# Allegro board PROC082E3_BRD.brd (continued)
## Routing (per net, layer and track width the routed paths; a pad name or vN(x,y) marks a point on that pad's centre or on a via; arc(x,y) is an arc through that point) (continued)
CSI0_D2_P: length 125.7
  TOP w0.102: J2.17 48.09,31.28 arc(48.06,31.42) 47.98,31.54 47.97,31.55 arc(47.89,31.68) 47.86,31.82 47.86,32.73 arc(47.9,32.84) 48.01,32.89 48.06,32.89 arc(48.14,32.87) 48.22,32.82 48.3,32.74 v1(48.3,32.69)
  L03_SIG1 w0.089: v1(50.95,94.7) arc(50.87,94.9) 50.66,94.98 50.04,94.98 arc(49.8,94.93) 49.59,94.8 49.35,94.55 arc(49.06,94.12) 48.95,93.6 48.95,91.41 arc(48.84,90.86) 48.53,90.38 46.65,88.5 arc(46.06,87.62) 45.85,86.58 45.85,79.54 arc(46.05,78.55) 46.61,77.71 51.4,72.92 arc(52.07,71.91) 52.3,70.72 52.3,56.23 arc(52.17,55.57) 51.8,55.01 arc(51.64,54.78) 51.59,54.51 51.59,51.96 arc(51.37,51.43) 50.85,51.21 49.62,51.21 arc(49.22,50.81) 49.62,50.41 51.51,50.41 arc(52.25,49.67) 51.51,48.93 49.62,48.93 arc(49.22,48.53) 49.62,48.13 50.85,48.13 arc(51.59,47.38) 50.85,46.64 49.62,46.64 arc(49.22,46.24) 49.62,45.84 50.85,45.84 arc(51.59,45.1) 50.85,44.35 49.62,44.35 arc(49.22,43.95) 49.62,43.55 50.85,43.55 arc(51.37,43.34) 51.59,42.81 51.59,41.84 arc(51.23,40.04) 50.21,38.51 arc(50.05,38.28) 50,38.01 50,37.68 arc(50.16,37.28) 50.56,37.12 51.67,37.12 arc(52.2,36.9) 52.42,36.37 52.42,35.16 arc(52.2,34.63) 51.67,34.41 49.36,34.41 arc(49.28,34.39) 49.22,34.35 48.13,33.26 arc(48.04,33.13) 48.01,32.98 arc(48.1,32.78) v1(48.3,32.69)
  BOTTOM w0.102: v1(50.95,94.7) 50.95,94.74 arc(50.87,94.93) 50.67,95.01 arc(50.36,95.08) 50.09,95.26 49.34,96.01 arc(49.15,96.3) 49.08,96.64 49.08,96.75 arc(48.98,97.26) 48.69,97.69 47.62,98.77 arc(46.93,99.23) 46.12,99.39 43.05,99.39 arc(42.28,99.54) 41.63,99.98 41.04,100.56 arc(40.48,100.94) 39.81,101.07 37.83,101.07 arc(37.39,101.16) 37.02,101.41 arc(36.12,102.01) 35.06,102.22 33.31,102.22 arc(31.43,102.6) 29.84,103.66 29.08,104.42 arc(28.76,104.9) 28.64,105.47 28.64,106.17 arc(28.55,106.65) 28.28,107.06 28.18,107.15 arc(28,107.42) 27.94,107.73 27.94,110.63 arc(27.93,110.67) 27.91,110.7 27.85,110.76 arc(27.83,110.79) 27.82,110.83 U9.40
CSI0_D3_N: length 125.7
  TOP w0.102: J2.23 46.09,31.13 arc(46.1,31.2) 46.14,31.26 46.16,31.27 arc(46.19,31.33) 46.21,31.4 46.21,32 arc(46.15,32.14) 46.01,32.2 45.52,32.2 arc(45.33,32.17) 45.16,32.06 v1(44.99,31.88)
  L03_SIG1 w0.089: v1(44.99,31.88) 45.14,32.04 arc(45.29,32.13) 45.46,32.17 45.63,32.17 arc(45.91,32.22) 46.15,32.38 46.31,32.54 arc(46.48,32.8) 46.54,33.11 46.54,36.41 arc(46.73,37.37) 47.28,38.18 arc(47.66,38.75) 47.8,39.43 47.8,40.23 arc(47.91,40.51) 48.2,40.63 49.15,40.63 arc(49.89,41.37) 49.15,42.12 48.2,42.12 arc(47.91,42.23) 47.8,42.52 47.8,43.33 arc(47.58,43.86) 47.05,44.08 45.87,44.08 arc(45.62,44.18) 45.51,44.44 45.51,44.54 arc(45.61,44.78) 45.85,44.88 47.05,44.88 arc(47.58,45.1) 47.8,45.62 47.8,46.47 arc(47.53,47.1) 46.9,47.37 45.46,47.37 arc(44.9,47.92) 45.46,48.47 46.9,48.47 arc(47.8,49.37) 46.9,50.26 45.46,50.26 arc(44.9,50.81) 45.46,51.37 46.9,51.37 arc(47.53,51.63) 47.8,52.26 47.8,52.86 arc(48.22,55.01) 49.44,56.84 49.98,57.37 arc(50.48,58.12) 50.65,59 50.65,61.78 arc(50.55,62.31) 50.25,62.76 50.17,62.84 arc(50.03,63.04) 49.99,63.27 49.99,64.81 arc(50.07,65.23) 50.31,65.59 50.68,65.96 arc(50.96,66.37) 51.05,66.86 51.05,69.85 arc(50.96,70.34) 50.68,70.76 50.38,71.05 arc(50.18,71.18) 49.95,71.23 48.98,71.23 arc(48.66,71.29) 48.39,71.48 48.26,71.6 arc(48.11,71.82) 48.06,72.07 48.06,72.38 arc(48.01,72.63) 47.87,72.85 44.59,76.13 arc(44.19,76.72) 44.05,77.43 44.05,78.37 arc(43.71,79.18) 42.9,79.52 41.72,79.52 arc(40.91,80.33) 41.72,81.13 42.9,81.13 arc(43.71,81.47) 44.05,82.28 44.05,87.18 arc(44.15,87.69) 44.44,88.12 46.5,90.18 arc(46.89,90.77) 47.03,91.47 47.03,96.83 arc(47.12,97.03) v1(47.32,97.12)
  BOTTOM w0.102: v1(47.32,97.12) 47.26,97.12 arc(47.07,97.19) 46.99,97.38 46.99,97.61 arc(46.95,97.8) 46.84,97.97 46.74,98.07 arc(46.52,98.22) 46.25,98.28 38.94,98.28 arc(38,98.46) 37.21,98.99 36.46,99.75 arc(35.1,100.65) 33.49,100.97 33.06,100.97 arc(30.93,101.4) 29.13,102.6 arc(27.71,104.73) 27.21,107.24 27.21,110.63 arc(27.22,110.67) 27.24,110.7 27.29,110.76 arc(27.32,110.79) 27.32,110.83 U9.41
CSI0_D3_P: length 125.7
  TOP w0.102: v1(44.99,32.79) 44.99,32.57 arc(45.02,32.5) 45.09,32.47 46.01,32.47 arc(46.34,32.33) 46.47,32 46.47,31.37 arc(46.49,31.3) 46.53,31.24 46.54,31.23 arc(46.58,31.17) 46.59,31.11 J2.21
  L03_SIG1 w0.089: v1(44.99,32.79) 45.14,32.64 arc(45.29,32.54) 45.46,32.51 45.63,32.51 arc(45.78,32.54) 45.91,32.63 46.06,32.78 arc(46.16,32.93) 46.2,33.11 46.2,36.41 arc(46.42,37.5) 47.04,38.42 arc(47.34,38.88) 47.45,39.43 47.45,40.23 arc(47.67,40.76) 48.2,40.97 49.15,40.97 arc(49.55,41.37) 49.15,41.77 48.2,41.77 arc(47.67,41.99) 47.45,42.52 47.45,43.33 arc(47.34,43.62) 47.05,43.73 45.87,43.73 arc(45.38,43.94) 45.17,44.44 45.17,44.54 arc(45.37,45.02) 45.85,45.22 47.05,45.22 arc(47.34,45.34) 47.45,45.62 47.45,46.47 arc(47.29,46.86) 46.9,47.02 45.46,47.02 arc(44.56,47.92) 45.46,48.81 46.9,48.81 arc(47.45,49.37) 46.9,49.92 45.46,49.92 arc(44.56,50.81) 45.46,51.71 46.9,51.71 arc(47.29,51.87) 47.45,52.26 47.45,52.86 arc(47.91,55.14) 49.2,57.08 49.74,57.62 arc(50.16,58.25) 50.31,59 50.31,61.78 arc(50.23,62.18) 50.01,62.51 49.92,62.59 arc(49.72,62.9) 49.65,63.27 49.65,64.81 arc(49.76,65.36) 50.07,65.83 50.43,66.2 arc(50.64,66.5) 50.71,66.86 50.71,69.85 arc(50.64,70.21) 50.43,70.52 50.14,70.81 arc(50.05,70.87) 49.95,70.89 48.98,70.89 arc(48.53,70.98) 48.15,71.23 48.02,71.36 arc(47.8,71.69) 47.72,72.07 47.72,72.38 arc(47.7,72.5) 47.63,72.6 47.43,72.8 44.35,75.88 arc(43.87,76.59) 43.71,77.43 43.71,78.37 arc(43.47,78.94) 42.9,79.18 41.72,79.18 arc(40.57,80.33) 41.72,81.47 42.9,81.47 arc(43.47,81.71) 43.71,82.28 43.71,87.18 arc(43.83,87.82) 44.2,88.36 46.25,90.42 arc(46.58,90.9) 46.69,91.47 46.69,96.83 arc(46.6,97.03) v1(46.4,97.12)
  BOTTOM w0.102: U9.42 26.82,110.83 arc(26.83,110.79) 26.85,110.76 26.91,110.7 arc(26.93,110.67) 26.94,110.63 26.94,107.24 arc(27.46,104.63) 28.94,102.41 arc(30.83,101.15) 33.06,100.71 33.49,100.71 arc(34.99,100.41) 36.27,99.56 37.02,98.8 arc(37.9,98.21) 38.94,98.01 46.25,98.01 arc(46.41,97.98) 46.55,97.88 46.66,97.78 arc(46.71,97.7) 46.73,97.61 46.73,97.38 arc(46.65,97.19) 46.46,97.12 v1(46.4,97.12)
CSI1_CLK_N: length 55.7
  TOP w0.102: J2.27 44.59,29.7 arc(44.6,29.63) 44.64,29.58 44.66,29.56 arc(44.69,29.51) 44.71,29.44 44.71,28.46 arc(44.67,28.26) 44.56,28.1 v1(44.38,27.92)
  L6_SIG2 w0.089: v1(30.82,63.21) 30.98,63.21 arc(31.11,63.27) 31.17,63.4 31.17,63.49 arc(31.11,63.62) 30.99,63.67 30.51,63.67 arc(30.37,63.65) 30.24,63.56 30.16,63.49 arc(30.02,63.27) 29.97,63.02 29.97,58.98 arc(30.02,58.75) 30.15,58.55 32.03,56.67 arc(32.48,55.99) 32.64,55.2 32.64,40.38 arc(32.75,39.82) 33.07,39.34 33.26,39.15 38.41,34 arc(38.9,33.26) 39.08,32.4 39.08,30.76 arc(39.21,30.43) 39.53,30.3 41.38,30.3 arc(41.99,30.04) 42.25,29.43 42.25,27.61 arc(42.44,27.15) 42.9,26.96 44.72,26.96 arc(44.88,27.02) 44.94,27.18 44.94,27.29 arc(44.9,27.39) 44.8,27.43 44.36,27.43 arc(44.26,27.47) 44.22,27.57 44.22,27.78 arc(44.26,27.88) 44.36,27.92 v1(44.38,27.92)
  BOTTOM w0.102: U24.31 34.5,63.07 arc(34.46,63.08) 34.43,63.1 34.37,63.16 arc(34.34,63.18) 34.3,63.19 32.52,63.19 arc(32.12,63.27) 31.79,63.49 arc(31.74,63.52) 31.68,63.54 31.19,63.54 arc(31.15,63.53) 31.12,63.51 v1(30.82,63.21)
CSI1_CLK_P: length 55.7
  TOP w0.102: J2.25 45.09,29.7 arc(45.08,29.63) 45.04,29.58 45.03,29.56 arc(44.99,29.51) 44.97,29.44 44.97,28.46 arc(45.01,28.26) 45.12,28.1 v1(45.3,27.92)
  L6_SIG2 w0.089: v1(45.3,27.92) 45.2,27.83 arc(45.15,27.7) 45.2,27.58 arc(45.26,27.49) 45.29,27.38 45.29,27.18 arc(45.12,26.78) 44.72,26.62 42.9,26.62 arc(42.2,26.91) 41.91,27.61 41.91,29.43 arc(41.75,29.8) 41.38,29.96 39.53,29.96 arc(38.97,30.19) 38.73,30.76 38.73,32.4 arc(38.59,33.13) 38.17,33.75 33.02,38.91 32.83,39.1 arc(32.43,39.69) 32.29,40.38 32.29,55.2 arc(32.16,55.86) 31.79,56.42 29.91,58.31 arc(29.7,58.61) 29.63,58.98 29.63,63.02 arc(29.7,63.4) 29.92,63.73 30,63.8 arc(30.23,63.96) 30.51,64.02 30.56,64.02 arc(30.7,64.05) v1(30.82,64.13)
  BOTTOM w0.102: U24.32 34.5,63.57 arc(34.46,63.56) 34.43,63.54 34.37,63.48 arc(34.34,63.46) 34.3,63.46 32.52,63.46 arc(32.23,63.51) 31.98,63.68 arc(31.84,63.77) 31.68,63.8 31.19,63.8 arc(31.15,63.81) 31.12,63.83 v1(30.82,64.13)
CSI1_D0_N: length 55.8
  TOP w0.102: v1(42.88,29.13) 43.08,29.13 arc(43.17,29.17) 43.21,29.26 43.21,29.47 arc(43.2,29.51) 43.18,29.54 43.12,29.6 arc(43.1,29.63) 43.09,29.67 J2.31
  L6_SIG2 w0.089: v1(42.88,29.13) 42.88,29.1 arc(42.93,28.98) 43.05,28.93 43.15,28.93 arc(43.27,28.98) 43.32,29.1 43.32,30.84 arc(43.21,31.09) 42.96,31.2 40.81,31.2 arc(40.2,31.45) 39.95,32.06 39.95,33.46 arc(39.88,33.82) 39.67,34.14 34.48,39.33 arc(34.25,39.67) 34.17,40.07 34.17,57.65 arc(34.08,57.87) 33.86,57.96 32.66,57.96 arc(32,58.61) 32.66,59.27 33.86,59.27 arc(34.08,59.36) 34.17,59.58 34.17,60.25 arc(34.03,60.6) 33.68,60.74 31.52,60.74 arc(31.07,60.93) 30.88,61.38 30.88,61.52 arc(31.08,61.99) 31.55,62.18 33.61,62.18 arc(33.79,62.26) 33.87,62.44 33.87,64.26 arc(33.8,64.43) 33.62,64.5 33.08,64.5 arc(32.94,64.47) 32.81,64.39 v1(32.63,64.21)
  BOTTOM w0.102: v1(32.63,64.21) 32.92,64.5 arc(32.96,64.52) 33,64.53 33.11,64.53 arc(33.27,64.5) 33.42,64.4 arc(33.65,64.24) 33.93,64.19 34.3,64.19 arc(34.34,64.18) 34.37,64.16 34.43,64.1 arc(34.46,64.08) 34.5,64.07 U24.33
CSI1_D0_P: length 55.7
  TOP w0.102: J2.29 43.59,29.67 arc(43.58,29.63) 43.56,29.6 43.5,29.54 arc(43.48,29.51) 43.47,29.47 43.47,29.26 arc(43.51,29.17) 43.61,29.13 v1(43.8,29.13)
  L6_SIG2 w0.089: v1(43.8,29.13) 43.76,29.17 arc(43.69,29.28) 43.66,29.4 43.66,30.84 arc(43.45,31.34) 42.96,31.54 40.81,31.54 arc(40.45,31.69) 40.29,32.06 40.29,33.46 arc(40.2,33.96) 39.91,34.38 34.72,39.57 arc(34.57,39.8) 34.52,40.07 34.52,57.65 arc(34.32,58.11) 33.86,58.3 32.66,58.3 arc(32.35,58.61) 32.66,58.92 33.86,58.92 arc(34.32,59.11) 34.52,59.58 34.52,60.25 arc(34.27,60.84) 33.68,61.08 31.52,61.08 arc(31.31,61.17) 31.23,61.38 31.23,61.52 arc(31.32,61.75) 31.55,61.84 33.61,61.84 arc(34.03,62.02) 34.21,62.44 34.21,64.26 arc(34.04,64.67) 33.62,64.84 33.08,64.84 arc(32.92,64.88) 32.79,64.97 v1(32.63,65.12)
  BOTTOM w0.102: U24.34 34.5,64.57 arc(34.46,64.56) 34.43,64.54 34.37,64.48 arc(34.34,64.46) 34.3,64.46 33.93,64.46 arc(33.76,64.49) 33.6,64.59 arc(33.38,64.74) 33.11,64.8 33,64.8 arc(32.96,64.81) 32.92,64.83 v1(32.63,65.12)
CSI1_D1_N: length 56.1
  TOP w0.102: J2.35 41.59,31.45 arc(41.6,31.52) 41.64,31.58 41.66,31.59 arc(41.69,31.65) 41.71,31.71 41.71,31.81 arc(41.68,31.94) 41.6,32.06 v1(41.38,32.28)
  L6_SIG2 w0.089: v1(30.82,65.38) 31.08,65.64 arc(31.19,65.71) 31.32,65.74 33.47,65.74 arc(33.69,65.78) 33.88,65.91 33.94,65.97 arc(34.16,66.11) 34.41,66.16 35.48,66.16 arc(35.87,66) 36.03,65.62 36.03,62.82 arc(35.96,62.47) 35.76,62.18 arc(35.56,61.87) 35.49,61.51 35.49,46.42 arc(35.83,44.69) 36.81,43.22 37.12,42.91 arc(37.21,42.69) 37.12,42.47 36.64,41.99 arc(36.44,41.53) 36.64,41.06 arc(37.1,40.87) 37.56,41.06 38.04,41.55 arc(38.48,41.55) 38.48,41.11 38,40.62 arc(37.81,40.16) 38,39.7 arc(38.46,39.51) 38.93,39.7 39.41,40.18 arc(39.63,40.27) 39.85,40.18 40.72,39.31 arc(41.16,38.66) 41.31,37.89 41.31,37.52 arc(41.22,37.3) 41,37.21 40.25,37.21 arc(39.6,36.56) 40.25,35.9 41,35.9 arc(41.22,35.81) 41.31,35.59 41.31,33.76 arc(41.4,33.3) 41.67,32.9 arc(41.79,32.72) 41.83,32.5 41.83,32.28 arc(41.8,32.19) 41.71,32.16 41.51,32.16 arc(41.42,32.19) v1(41.38,32.28)
  BOTTOM w0.102: v1(30.82,65.38) 31.03,65.59 arc(31.18,65.69) 31.35,65.72 32.88,65.72 arc(32.98,65.7) 33.06,65.65 33.28,65.43 arc(33.55,65.25) 33.86,65.19 34.3,65.19 arc(34.34,65.18) 34.37,65.16 34.43,65.1 arc(34.46,65.08) 34.5,65.07 U24.35
CSI1_D1_P: length 56
  TOP w0.102: v1(42.3,32.28) 42.08,32.06 arc(42,31.94) 41.97,31.81 41.97,31.71 arc(41.99,31.65) 42.03,31.59 42.04,31.58 arc(42.08,31.52) 42.09,31.45 J2.33
  L6_SIG2 w0.089: v1(42.3,32.28) 42.24,32.33 arc(42.19,32.41) 42.17,32.5 arc(42.11,32.85) 41.91,33.15 arc(41.72,33.43) 41.65,33.76 41.65,35.59 arc(41.46,36.06) 41,36.25 40.25,36.25 arc(39.94,36.56) 40.25,36.87 41,36.87 arc(41.46,37.06) 41.65,37.52 41.65,37.89 arc(41.48,38.79) 40.97,39.55 40.09,40.42 arc(39.63,40.62) 39.17,40.42 38.68,39.94 arc(38.46,39.85) 38.24,39.94 arc(38.15,40.16) 38.24,40.38 38.73,40.86 arc(38.73,41.79) 37.8,41.79 37.32,41.31 arc(37.1,41.21) 36.88,41.31 arc(36.79,41.53) 36.88,41.75 37.36,42.23 arc(37.55,42.69) 37.36,43.15 37.06,43.46 arc(36.15,44.82) 35.83,46.42 35.83,61.51 arc(35.88,61.74) 36.01,61.94 arc(36.28,62.34) 36.37,62.82 36.37,65.62 arc(36.11,66.25) 35.48,66.51 34.41,66.51 arc(34.02,66.43) 33.7,66.21 33.64,66.16 arc(33.56,66.1) 33.47,66.08 31.32,66.08 arc(31.06,66.13) 30.84,66.28 v1(30.82,66.3)
  BOTTOM w0.102: U24.36 34.5,65.57 arc(34.46,65.56) 34.43,65.54 34.37,65.48 arc(34.34,65.46) 34.3,65.46 33.86,65.46 arc(33.65,65.5) 33.47,65.62 33.25,65.84 arc(33.08,65.95) 32.88,65.99 31.25,65.99 arc(31.14,66.01) 31.05,66.07 v1(30.82,66.3)
CSI1_D2_N: length 55.8
  TOP w0.102: v1(39.88,28.87) 40.18,29.17 arc(40.2,29.2) 40.21,29.24 40.21,29.47 arc(40.2,29.51) 40.18,29.54 40.12,29.6 arc(40.1,29.63) 40.09,29.67 J2.39
  L6_SIG2 w0.089: v1(32.57,66.58) 32.69,66.69 32.69,66.82 32.59,66.92 30.13,66.92 arc(29.76,66.84) 29.45,66.64 29.07,66.25 arc(28.82,65.89) 28.74,65.46 28.74,57.89 arc(28.88,57.19) 29.27,56.6 30.6,55.27 arc(30.9,54.82) 31.01,54.28 31.01,34.8 arc(31.17,34.02) 31.6,33.37 36.64,28.33 arc(37.27,27.91) 38.02,27.76 39.55,27.76 arc(39.86,27.82) 40.13,28 40.22,28.09 arc(40.32,28.24) 40.36,28.42 40.36,29.15 arc(40.32,29.23) 40.24,29.26 40,29.26 arc(39.92,29.23) 39.89,29.15 39.89,28.88 v1(39.88,28.87)
  BOTTOM w0.102: v1(32.57,66.58) 32.57,66.69 arc(32.67,66.91) 32.89,67.01 33.25,67.01 arc(33.41,67.04) 33.55,67.13 33.56,67.15 arc(33.61,67.18) 33.66,67.19 34.3,67.19 arc(34.34,67.18) 34.37,67.16 34.43,67.1 arc(34.46,67.08) 34.5,67.07 U24.39
CSI1_D2_P: length 55.8
  TOP w0.102: J2.37 40.59,29.67 arc(40.58,29.63) 40.56,29.6 40.5,29.54 arc(40.48,29.51) 40.47,29.47 40.47,29.24 arc(40.48,29.2) 40.5,29.17 v1(40.8,28.87)
  L6_SIG2 w0.089: v1(32.57,67.49) 32.34,67.26 30.13,67.26 arc(29.63,67.16) 29.21,66.88 28.83,66.5 arc(28.51,66.02) 28.39,65.46 28.39,57.89 arc(28.56,57.06) 29.03,56.36 30.36,55.03 arc(30.59,54.69) 30.67,54.28 30.67,34.8 arc(30.85,33.89) 31.36,33.12 36.4,28.09 arc(37.14,27.59) 38.02,27.42 39.55,27.42 arc(39.99,27.5) 40.37,27.75 40.46,27.85 arc(40.64,28.11) 40.7,28.42 40.7,28.78 arc(40.73,28.85) v1(40.8,28.87)
  BOTTOM w0.102: v1(32.57,67.49) 32.72,67.34 arc(32.8,67.29) 32.89,67.27 33.25,67.27 arc(33.31,67.28) 33.36,67.32 33.38,67.34 arc(33.51,67.42) 33.66,67.46 34.3,67.46 arc(34.34,67.46) 34.37,67.48 34.43,67.54 arc(34.46,67.56) 34.5,67.57 U24.40
CSI1_D3_N: length 55.9
  TOP w0.102: v1(44.4,41.01) 44.47,41.01 arc(44.64,40.94) 44.71,40.77 44.71,37.85 arc(44.7,37.81) 44.68,37.78 44.62,37.72 arc(44.6,37.69) 44.59,37.65 J2.28
  L6_SIG2 w0.089: v1(44.4,41.01) 44.4,40.98 arc(44.44,40.88) 44.54,40.84 44.74,40.84 arc(44.84,40.88) 44.88,40.98 44.88,47.7 arc(44.69,48.67) 44.14,49.48 42.77,50.86 arc(42.55,50.95) 42.33,50.86 41.71,50.24 arc(41.25,50.05) 40.79,50.24 arc(40.6,50.71) 40.79,51.17 41.4,51.78 arc(41.4,52.22) 40.96,52.22 40.35,51.61 arc(39.89,51.42) 39.42,51.61 arc(39.23,52.07) 39.42,52.53 40.04,53.15 arc(40.04,53.59) 39.6,53.59 38.98,52.97 arc(38.52,52.78) 38.06,52.97 arc(37.87,53.44) 38.06,53.9 38.67,54.51 arc(38.76,54.73) 38.67,54.95 38.22,55.4 arc(37.97,55.78) 37.88,56.22 37.88,57.18 arc(37.85,57.33) 37.77,57.45 37.62,57.61 arc(37.41,57.92) 37.34,58.28 37.34,68.43 arc(37.1,69) 36.53,69.24 34.98,69.24 arc(34.5,69.14) 34.1,68.87 33.74,68.51 arc(33.34,68.24) 32.87,68.15 31.25,68.15 arc(31.12,68.12) 31.01,68.05 v1(30.82,67.86)
  BOTTOM w0.102: U24.41 34.5,68.07 arc(34.46,68.08) 34.43,68.1 34.37,68.16 arc(34.34,68.18) 34.3,68.19 31.19,68.19 arc(31.15,68.18) 31.11,68.15 v1(30.82,67.86)
CSI1_D3_P: length 55.8
  TOP w0.102: J2.26 45.09,37.65 arc(45.08,37.69) 45.06,37.72 45,37.78 arc(44.98,37.81) 44.97,37.85 44.97,40.77 arc(45.04,40.94) 45.21,41.01 v1(45.32,41.01)
  L6_SIG2 w0.089: v1(30.82,68.78) 30.99,68.61 arc(31.12,68.52) 31.27,68.49 32.87,68.49 arc(33.21,68.56) 33.5,68.75 33.86,69.11 arc(34.37,69.46) 34.98,69.58 36.53,69.58 arc(37.34,69.24) 37.68,68.43 37.68,58.28 arc(37.73,58.05) 37.86,57.85 38.01,57.7 arc(38.17,57.46) 38.22,57.18 38.22,56.22 arc(38.29,55.91) 38.46,55.65 38.91,55.2 arc(39.11,54.73) 38.91,54.27 38.3,53.66 arc(38.21,53.44) 38.3,53.22 arc(38.52,53.13) 38.74,53.22 39.35,53.83 arc(40.28,53.83) 40.28,52.91 39.67,52.29 arc(39.58,52.07) 39.67,51.85 arc(39.89,51.76) 40.11,51.85 40.72,52.47 arc(41.64,52.47) 41.64,51.54 41.03,50.93 arc(40.94,50.71) 41.03,50.49 arc(41.25,50.4) 41.47,50.49 42.08,51.1 arc(42.55,51.29) 43.01,51.1 44.38,49.73 arc(45,48.8) 45.22,47.7 45.22,41.24 arc(45.25,41.11) v1(45.32,41.01)
  BOTTOM w0.102: v1(30.82,68.78) 31.11,68.49 arc(31.15,68.46) 31.19,68.46 34.3,68.46 arc(34.34,68.46) 34.37,68.48 34.43,68.54 arc(34.46,68.56) 34.5,68.57 U24.42
CSI2_0_CLK_N: length 93.4
  L6_SIG2 w0.089: v1(42.47,114.87) 42.73,114.61 arc(42.76,114.59) 42.79,114.58 43.13,114.58 arc(43.26,114.63) 43.31,114.75 43.31,124.24 arc(43.39,124.66) 43.62,125.01 43.9,125.28 arc(44.12,125.61) 44.2,126 44.2,128.98 arc(44.14,129.29) 43.96,129.55 43.1,130.41 arc(42.88,130.74) 42.8,131.13 42.8,135.65 arc(42.9,136.16) 43.19,136.59 43.84,137.24 arc(44.02,137.51) 44.08,137.82 44.08,143.51 arc(43.99,143.97) 43.73,144.35 42.18,145.9 arc(41.05,147.6) 40.65,149.6 40.65,162.57 arc(40.71,162.88) 40.89,163.14 41.36,163.62 arc(41.61,163.98) 41.69,164.42 41.69,169.61 arc(41.48,170.13) 40.96,170.35 37,170.35 arc(36.43,170.46) 35.95,170.78 32.54,174.19 arc(32.27,174.58) 32.18,175.05 32.18,178.63 arc(32.36,179.53) 32.87,180.29 37.11,184.54 arc(37.68,185.39) 37.88,186.39 37.88,186.61 arc(37.88,186.61) 37.88,186.62 37.88,187.23 arc(37.83,187.31) 37.73,187.29 v1(37.55,187.1)
  BOTTOM w0.102: v1(37.55,187.1) 37.84,187.4 37.86,187.42 arc(37.87,187.45) 37.87,187.47 37.87,188.16 arc(37.86,188.19) 37.84,188.23 37.78,188.28 arc(37.76,188.32) 37.76,188.36 J20.27 ; U9.17 37.65,114.66 arc(37.69,114.65) 37.72,114.63 37.78,114.57 arc(37.81,114.55) 37.85,114.54 42.1,114.54 arc(42.14,114.55) 42.17,114.57 v1(42.47,114.87)
CSI2_0_CLK_P: length 93.4
  L6_SIG2 w0.089: v1(38.46,187.1) 38.41,187.05 arc(38.27,186.85) 38.23,186.62 38.23,186.39 arc(38,185.26) 37.36,184.29 33.11,180.05 arc(32.68,179.4) 32.52,178.63 32.52,175.05 arc(32.59,174.72) 32.78,174.43 36.19,171.02 arc(36.56,170.77) 37,170.69 40.96,170.69 arc(41.72,170.37) 42.04,169.61 42.04,164.42 arc(41.92,163.85) 41.61,163.37 41.13,162.9 arc(41.03,162.75) 41,162.57 41,149.6 arc(41.37,147.73) 42.43,146.14 43.98,144.59 arc(44.31,144.1) 44.42,143.51 44.42,137.82 arc(44.34,137.37) 44.08,136.99 43.43,136.34 arc(43.22,136.02) 43.14,135.65 43.14,131.13 arc(43.19,130.87) 43.34,130.65 44.2,129.79 arc(44.45,129.42) 44.54,128.98 44.54,126 arc(44.44,125.48) 44.14,125.04 43.87,124.77 arc(43.71,124.53) 43.65,124.24 43.65,114.75 arc(43.5,114.39) 43.13,114.24 42.79,114.24 arc(42.76,114.23) 42.73,114.21 v1(42.47,113.95)
  BOTTOM w0.102: v1(42.47,113.95) 42.17,114.25 arc(42.14,114.27) 42.1,114.28 37.85,114.28 arc(37.81,114.27) 37.78,114.25 37.72,114.19 arc(37.69,114.17) 37.65,114.16 U9.18 ; v1(38.46,187.1) 38.17,187.4 38.15,187.42 arc(38.14,187.45) 38.14,187.47 38.14,188.16 arc(38.15,188.19) 38.17,188.23 38.23,188.28 arc(38.25,188.32) 38.26,188.36 J20.25
CSI2_0_D0_N: length 93.3
  L6_SIG2 w0.089: v1(39.15,113.59) 39.41,113.85 arc(39.43,113.88) 39.43,113.91 39.43,114.34 arc(39.56,114.64) 39.87,114.77 41.19,114.77 arc(41.4,114.86) 41.49,115.07 41.49,118.52 arc(41.46,118.67) 41.38,118.79 41.04,119.13 arc(40.85,119.42) 40.78,119.76 40.78,122.71 arc(40.85,123.05) 41.04,123.34 41.84,124.13 arc(42.17,124.64) 42.29,125.23 42.29,128.02 arc(42.21,128.41) 41.99,128.75 40.79,129.94 arc(40.63,130.19) 40.58,130.47 40.58,134.11 arc(40.63,134.38) 40.78,134.61 41.06,134.89 arc(41.2,135.1) 41.25,135.35 41.25,136.41 arc(41.33,136.82) 41.57,137.18 42.54,138.15 arc(42.65,138.31) 42.68,138.49 42.68,142.35 arc(42.61,142.75) 42.38,143.09 40.13,145.34 arc(39.66,146.04) 39.5,146.87 39.5,149.46 arc(39.42,149.85) 39.19,150.19 37.26,152.12 arc(36.98,152.54) 36.88,153.04 36.88,164.36 arc(36.96,164.74) 37.17,165.06 38.04,165.93 arc(38.1,166.08) 38.04,166.23 34.79,169.47 arc(34.67,169.55) 34.53,169.58 33.67,169.58 arc(33.29,169.66) 32.97,169.87 arc(32.87,169.94) 32.75,169.96 31.46,169.96 arc(31.06,170.13) 30.9,170.53 30.9,179.1 arc(31.04,179.81) 31.45,180.42 36.17,185.14 arc(36.39,185.46) 36.46,185.84 36.46,187.63 arc(36.32,187.85) 36.07,187.79 v1(36.02,187.75)
  BOTTOM w0.102: J20.31 36.26,188.36 arc(36.26,188.32) 36.28,188.28 36.34,188.23 arc(36.36,188.19) 36.37,188.16 36.37,187.96 arc(36.31,187.81) 36.16,187.75 v1(36.02,187.75) ; U9.19 37.65,113.66 arc(37.69,113.65) 37.72,113.63 37.78,113.57 arc(37.81,113.55) 37.85,113.54 38.06,113.54 arc(38.25,113.5) 38.42,113.4 38.81,113.01 arc(38.95,112.91) 39.12,112.88 39.23,112.88 arc(39.4,112.95) 39.47,113.12 39.47,113.22 arc(39.46,113.26) 39.44,113.29 v1(39.15,113.59)
CSI2_0_D0_P: length 93.2
  L6_SIG2 w0.089: v1(40.06,113.59) 39.8,113.85 arc(39.78,113.88) 39.78,113.91 39.78,114.34 arc(39.8,114.4) 39.87,114.43 41.19,114.43 arc(41.65,114.61) 41.83,115.07 41.83,118.52 arc(41.78,118.8) 41.62,119.04 41.29,119.37 arc(41.16,119.55) 41.12,119.76 41.12,122.71 arc(41.16,122.92) 41.28,123.09 42.08,123.89 arc(42.49,124.5) 42.63,125.23 42.63,128.02 arc(42.53,128.55) 42.23,129 41.04,130.19 arc(40.95,130.32) 40.92,130.47 40.92,134.11 arc(40.95,134.25) 41.03,134.37 41.3,134.65 arc(41.52,134.97) 41.59,135.35 41.59,136.41 arc(41.65,136.69) 41.81,136.93 42.79,137.91 arc(42.96,138.18) 43.03,138.49 43.03,142.35 arc(42.92,142.88) 42.62,143.33 40.38,145.58 arc(39.98,146.17) 39.84,146.87 39.84,149.46 arc(39.73,149.98) 39.44,150.43 37.5,152.36 arc(37.3,152.67) 37.22,153.04 37.22,161.53 37.22,164.36 arc(37.27,164.61) 37.41,164.82 38.28,165.68 arc(38.44,166.08) 38.28,166.47 35.03,169.72 arc(34.8,169.87) 34.53,169.93 33.67,169.93 arc(33.42,169.98) 33.21,170.12 arc(33,170.26) 32.75,170.31 31.46,170.31 arc(31.31,170.37) 31.24,170.53 31.24,179.1 arc(31.36,179.68) 31.69,180.18 36.42,184.9 arc(36.7,185.33) 36.8,185.84 36.8,187.43 arc(36.84,187.61) v1(36.94,187.75)
  BOTTOM w0.102: v1(36.94,187.75) 36.85,187.75 arc(36.7,187.81) 36.64,187.96 36.64,188.16 arc(36.65,188.19) 36.67,188.23 36.73,188.28 arc(36.75,188.32) 36.76,188.36 J20.29 ; v1(40.06,113.59) 39.77,113.29 arc(39.75,113.26) 39.74,113.22 39.74,113.12 arc(39.59,112.76) 39.23,112.61 39.12,112.61 arc(38.85,112.66) 38.62,112.82 38.23,113.21 arc(38.15,113.26) 38.06,113.28 37.85,113.28 arc(37.81,113.27) 37.78,113.25 37.72,113.19 arc(37.69,113.17) 37.65,113.16 U9.20
CSI2_0_D1_N: length 93.4
  L6_SIG2 w0.089: v1(37.54,110.24) 37.46,110.31 arc(37.33,110.4) 37.19,110.43 36.56,110.43 arc(36.04,110.64) 35.83,111.16 35.83,116.86 arc(35.95,117.46) 36.29,117.97 38.54,120.23 arc(38.92,120.79) 39.05,121.46 39.05,135.44 arc(39.23,136.34) 39.74,137.1 arc(39.95,137.42) 40.03,137.81 40.03,139.12 arc(39.87,139.94) 39.41,140.63 38.74,141.29 arc(38.44,141.75) 38.33,142.29 38.33,147.33 arc(38.13,148.33) 37.57,149.17 36.33,150.41 arc(35.43,151.76) 35.12,153.34 35.12,165.9 arc(34.92,166.86) 34.38,167.68 33.78,168.28 arc(33.22,168.65) 32.56,168.78 30.73,168.78 arc(30.12,169.04) 29.87,169.65 29.87,179.83 arc(29.96,180.25) 30.2,180.62 34.05,184.47 arc(34.49,185.13) 34.65,185.9 34.65,186.87 arc(34.62,187) v1(34.55,187.1)
  BOTTOM w0.102: U9.21 37.65,112.66 arc(37.69,112.65) 37.72,112.63 37.78,112.57 arc(37.81,112.55) 37.85,112.54 38.13,112.54 arc(38.46,112.4) 38.6,112.07 38.6,110.97 arc(38.45,110.62) 38.1,110.48 37.87,110.48 arc(37.79,110.46) 37.72,110.42 v1(37.54,110.24) ; J20.35 34.76,188.36 arc(34.76,188.32) 34.78,188.28 34.84,188.23 arc(34.86,188.19) 34.87,188.16 34.87,187.47 arc(34.87,187.45) 34.86,187.42 34.84,187.4 v1(34.55,187.1)
CSI2_0_D1_P: length 93.3
  L6_SIG2 w0.089: v1(37.54,111.15) 37.54,110.88 arc(37.5,110.8) 37.42,110.77 36.56,110.77 arc(36.28,110.88) 36.17,111.16 36.17,116.86 arc(36.26,117.33) 36.53,117.73 38.79,119.99 arc(39.24,120.66) 39.4,121.46 39.4,135.44 arc(39.55,136.21) 39.98,136.86 arc(40.27,137.29) 40.37,137.81 40.37,139.12 arc(40.18,140.07) 39.65,140.87 38.99,141.53 arc(38.75,141.88) 38.67,142.29 38.67,147.33 arc(38.45,148.46) 37.81,149.42 36.57,150.66 arc(35.75,151.89) 35.46,153.34 35.46,165.9 arc(35.24,166.99) 34.62,167.92 34.02,168.52 arc(33.35,168.97) 32.56,169.13 30.73,169.13 arc(30.37,169.28) 30.21,169.65 30.21,179.83 arc(30.27,180.12) 30.44,180.37 34.3,184.23 arc(34.3,184.23) 34.3,184.23 arc(34.81,185) 34.99,185.9 34.99,187.22 arc(35.08,187.36) 35.24,187.33 v1(35.46,187.1)
  BOTTOM w0.102: v1(35.46,187.1) 35.17,187.4 35.15,187.42 arc(35.14,187.45) 35.14,187.47 35.14,188.16 arc(35.15,188.19) 35.17,188.23 35.23,188.28 arc(35.25,188.32) 35.26,188.36 J20.33 ; U9.22 37.65,112.16 arc(37.69,112.17) 37.72,112.19 37.78,112.25 arc(37.81,112.27) 37.85,112.28 38.13,112.28 arc(38.27,112.22) 38.33,112.07 38.33,110.97 arc(38.26,110.81) 38.1,110.74 37.64,110.74 arc(37.57,110.77) 37.54,110.85 v1(37.54,111.15)
CSI2_0_D2_N: length 93.5
  L6_SIG2 w0.089: v1(33.02,187.75) arc(33.13,187.59) 33.17,187.39 33.17,186.39 arc(33,185.54) 32.52,184.82 30.62,182.92 arc(28.84,180.26) 28.22,177.12 28.22,167.27 arc(28.76,164.54) 30.31,162.22 32.03,160.5 arc(33.07,158.94) 33.44,157.09 33.44,153.39 arc(33.9,151.08) 35.21,149.12 arc(36.62,147) 37.12,144.5 37.12,125.79 arc(36.89,124.6) 36.21,123.59 35.33,122.7 arc(34.78,121.88) 34.58,120.9 34.58,114.68 arc(34.51,114.34) 34.32,114.06 33.48,113.21 arc(33.07,112.6) 32.93,111.89 32.93,111.05 arc(32.99,110.75) 33.16,110.5 33.31,110.35 arc(33.5,110.07) 33.57,109.73 33.57,108.96 arc(33.95,108.03) 34.88,107.65 35.36,107.65 arc(35.8,107.83) 35.98,108.27 35.98,108.32 arc(36.02,108.53) v1(36.14,108.7)
  BOTTOM w0.102: v1(33.02,187.75) 33.16,187.75 arc(33.31,187.81) 33.37,187.96 33.37,188.16 arc(33.36,188.19) 33.34,188.23 33.28,188.28 arc(33.26,188.32) 33.26,188.36 J20.39 ; U9.25 35.32,110.83 arc(35.32,110.79) 35.29,110.76 35.24,110.7 arc(35.22,110.67) 35.21,110.63 35.21,110.52 arc(35.24,110.37) 35.32,110.24 35.64,109.93 arc(35.77,109.73) 35.81,109.5 35.81,109.07 arc(35.82,109.04) 35.83,109.02 35.84,109 v1(36.14,108.7)
CSI2_0_D2_P: length 93.4
  L6_SIG2 w0.089: v1(35.22,108.7) 35.48,108.7 arc(35.59,108.66) 35.64,108.55 35.64,108.27 arc(35.55,108.07) 35.36,107.99 34.88,107.99 arc(34.19,108.27) 33.91,108.96 33.91,109.73 arc(33.82,110.2) 33.55,110.6 33.4,110.74 arc(33.31,110.88) 33.27,111.05 33.27,111.89 arc(33.39,112.47) 33.72,112.97 34.57,113.81 arc(34.83,114.21) 34.92,114.68 34.92,120.9 arc(35.09,121.75) 35.57,122.46 36.45,123.34 arc(37.2,124.46) 37.47,125.79 37.47,144.5 arc(36.94,147.13) 35.45,149.36 arc(34.22,151.21) 33.78,153.39 33.78,157.09 arc(33.39,159.07) 32.27,160.75 30.56,162.46 arc(29.08,164.67) 28.56,167.27 28.56,177.12 arc(29.16,180.13) 30.86,182.68 32.77,184.58 arc(33.32,185.41) 33.52,186.39 33.52,187.89 arc(33.53,187.94) 33.55,187.99 arc(33.63,188.02) 33.7,187.99 v1(33.94,187.75)
  BOTTOM w0.102: v1(35.22,108.7) 35.52,109 35.54,109.02 arc(35.54,109.04) 35.55,109.07 35.55,109.5 arc(35.52,109.63) 35.45,109.74 35.14,110.05 arc(34.99,110.27) 34.94,110.52 34.94,110.63 arc(34.93,110.67) 34.91,110.7 34.85,110.76 arc(34.83,110.79) 34.82,110.83 U9.26 ; J20.37 33.76,188.36 arc(33.75,188.32) 33.73,188.28 33.67,188.23 arc(33.65,188.19) 33.64,188.16 33.64,187.96 arc(33.7,187.81) 33.85,187.75 v1(33.94,187.75)
CSI2_0_D3_N: length 93.3
  L6_SIG2 w0.089: v1(37.52,181.58) 37.63,181.69 arc(37.81,181.73) 37.91,181.58 37.91,181.13 arc(38.35,180.07) 39.41,179.63 40.93,179.63 arc(42.62,178.93) 43.32,177.24 43.32,164.29 arc(43.28,164.09) 43.17,163.92 arc(42.96,163.61) 42.89,163.25 42.89,155.34 arc(42.94,155.07) 43.09,154.85 43.62,154.32 arc(43.81,154.03) 43.88,153.7 43.88,148.33 arc(44.06,147.41) 44.59,146.62 45.76,145.44 arc(45.98,145.13) 46.05,144.75 46.05,135.11 arc(46.2,134.38) 46.61,133.75 46.79,133.58 arc(47.24,132.9) 47.4,132.11 47.4,130.51 arc(47.34,130.25) 47.19,130.02 46.25,129.08 arc(45.88,128.52) 45.75,127.86 45.75,125.5 arc(45.69,125.25) 45.55,125.03 45.09,124.57 arc(44.87,124.24) 44.79,123.85 44.79,110.11 arc(44.66,109.79) 44.33,109.65 34.72,109.65 arc(34.6,109.7) 34.55,109.82 v1(34.55,110.09)
  BOTTOM w0.102: J20.28 37.76,182.19 arc(37.76,182.15) 37.78,182.11 37.84,182.06 arc(37.86,182.02) 37.87,181.99 37.87,181.79 arc(37.81,181.64) 37.66,181.58 v1(37.52,181.58) ; v1(34.55,110.09) 34.26,109.8 34.24,109.78 arc(34.21,109.77) 34.19,109.77 arc(33.98,109.85) 33.9,110.06 33.9,110.14 arc(33.93,110.34) 34.04,110.5 arc(34.17,110.68) 34.21,110.9 34.21,111.13 arc(34.24,111.28) U9.27
CSI2_0_D3_P: length 93.5
  L6_SIG2 w0.089: v1(38.44,181.58) 38.31,181.45 arc(38.27,181.39) 38.25,181.32 38.25,181.13 arc(38.59,180.31) 39.41,179.97 40.93,179.97 arc(42.86,179.17) 43.66,177.24 43.66,164.29 arc(43.6,163.96) 43.41,163.68 arc(43.28,163.48) 43.23,163.25 43.23,155.34 arc(43.26,155.2) 43.33,155.09 43.87,154.56 arc(44.13,154.17) 44.22,153.7 44.22,148.33 arc(44.38,147.54) 44.83,146.86 46.01,145.69 arc(46.29,145.26) 46.39,144.75 46.39,135.11 arc(46.51,134.51) 46.86,134 47.03,133.82 arc(47.55,133.03) 47.74,132.11 47.74,130.51 arc(47.66,130.12) 47.44,129.78 46.49,128.84 arc(46.19,128.39) 46.09,127.86 46.09,125.5 arc(46.01,125.11) 45.79,124.79 45.33,124.33 arc(45.19,124.11) 45.14,123.85 45.14,110.11 arc(44.9,109.54) 44.33,109.31 34.88,109.31 arc(34.7,109.27) v1(34.55,109.18)
  BOTTOM w0.102: v1(38.44,181.58) 38.35,181.58 arc(38.2,181.64) 38.14,181.79 38.14,181.99 arc(38.15,182.02) 38.17,182.06 38.23,182.11 arc(38.25,182.15) 38.26,182.19 J20.26 ; v1(34.55,109.18) 34.26,109.47 34.24,109.49 arc(34.21,109.5) 34.19,109.5 arc(33.79,109.66) 33.63,110.06 33.63,110.14 arc(33.69,110.44) 33.86,110.69 arc(33.92,110.79) 33.94,110.9 33.94,111.13 arc(33.91,111.28) U9.28
CSI2_CLK_N: length 83.9
  TOP w0.102: J1.7 55.08,85.61 arc(55.05,85.74) 54.98,85.84 v1(54.87,85.95)
  L6_SIG2 w0.089: v1(16.56,48.02) 16.48,48.1 arc(16.39,48.23) 16.36,48.39 arc(16.45,48.62) 16.68,48.71 23.75,48.71 arc(24.29,48.82) 24.75,49.13 26.53,50.91 arc(26.73,51.2) 26.79,51.55 26.79,54.93 arc(26.86,55.26) 27.05,55.55 27.13,55.62 arc(27.33,55.93) 27.41,56.3 27.41,66.4 arc(27.46,66.65) 27.6,66.86 27.7,66.97 arc(27.89,67.26) 27.96,67.6 27.96,76.17 arc(28.03,76.52) 28.23,76.82 30.82,79.4 arc(31.11,79.6) 31.45,79.66 38.88,79.66 arc(39.44,79.55) 39.91,79.23 40.19,78.96 arc(40.76,78.58) 41.43,78.44 55.46,78.44 arc(56.55,78.9) 57.01,79.99 57.01,86.42 arc(56.84,86.82) 56.43,86.99 55.67,86.99 arc(55.24,86.82) 55.07,86.39 55.07,86.15 arc(55.01,86.01) v1(54.87,85.95)
  BOTTOM w0.102: v1(16.56,48.02) 16.26,48.31 arc(16.24,48.35) 16.23,48.39 16.23,50.41 arc(16.24,50.45) 16.26,50.48 16.32,50.54 arc(16.34,50.57) 16.35,50.61 U25.31
CSI2_CLK_P: length 83.9
  TOP w0.102: v1(55.79,85.95) 55.52,85.95 arc(55.4,85.9) 55.34,85.77 55.34,85.52 arc(55.37,85.38) 55.45,85.26 55.47,85.24 arc(55.55,85.12) 55.58,84.98 J1.5
  L6_SIG2 w0.089: v1(55.79,85.95) 55.79,85.9 arc(55.74,85.8) 55.63,85.75 55.56,85.75 arc(55.45,85.8) 55.41,85.9 55.41,86.39 arc(55.49,86.57) 55.67,86.65 56.43,86.65 arc(56.6,86.58) 56.67,86.42 56.67,79.99 arc(56.31,79.14) 55.46,78.79 41.43,78.79 arc(40.89,78.89) 40.44,79.2 40.16,79.48 arc(39.57,79.87) 38.88,80.01 31.45,80.01 arc(30.97,79.91) 30.57,79.64 27.99,77.06 arc(27.72,76.65) 27.62,76.17 27.62,67.6 arc(27.58,67.39) 27.46,67.21 27.36,67.11 arc(27.14,66.78) 27.06,66.4 27.06,56.3 arc(27.02,56.06) 26.89,55.87 26.81,55.79 arc(26.54,55.39) 26.45,54.93 26.45,51.55 arc(26.41,51.34) 26.29,51.16 24.5,49.37 arc(24.16,49.14) 23.75,49.06 16.68,49.06 arc(16.21,48.86) 16.01,48.39 arc(15.9,48.13) v1(15.64,48.02)
  BOTTOM w0.102: U25.32 15.85,50.61 arc(15.86,50.57) 15.88,50.54 15.93,50.48 arc(15.96,50.45) 15.96,50.41 15.96,48.39 arc(15.96,48.35) 15.93,48.31 v1(15.64,48.02)
CSI2_D0_N: length 84
  TOP w0.102: v1(53.37,82.55) 53.48,82.66 arc(53.55,82.77) 53.58,82.9 J1.11
  L6_SIG2 w0.089: v1(53.37,82.55) 53.38,82.56 arc(53.5,82.74) 53.54,82.95 53.54,83.14 arc(53.69,83.5) 54.05,83.65 54.86,83.65 arc(55.33,83.46) 55.52,82.99 55.52,82.05 arc(55.44,81.64) 55.21,81.29 54.46,80.54 arc(54.2,80.37) 53.9,80.31 53.13,80.31 arc(52.95,80.28) 52.79,80.17 52.73,80.11 arc(52.32,79.84) 51.84,79.74 42.67,79.74 arc(41.98,79.88) 41.39,80.27 41.06,80.6 arc(40.63,80.89) 40.13,80.98 31.43,80.98 arc(30.68,80.84) 30.05,80.41 29.07,79.44 arc(28.61,79.24) 28.15,79.44 27.74,79.85 arc(27.52,79.94) 27.3,79.85 arc(27.21,79.63) 27.3,79.41 27.71,79 arc(27.9,78.53) 27.71,78.07 27.31,77.67 arc(26.65,76.68) 26.41,75.52 26.41,63.28 arc(26.3,62.7) 25.97,62.22 25.8,62.04 arc(25.55,61.67) 25.46,61.23 25.46,53.23 arc(25.28,52.31) 24.75,51.52 23.9,50.67 arc(23.14,50.17) 22.25,49.99 21.87,49.99 arc(21.41,50.18) 21.22,50.64 21.22,51.47 arc(20.91,51.78) 20.6,51.47 20.6,50.8 arc(19.94,50.15) 19.29,50.8 19.29,51.47 arc(18.98,51.78) 18.67,51.47 18.67,50.64 arc(18.47,50.18) 18.01,49.99 15.57,49.99 arc(15.35,49.89) 15.25,49.67 15.25,49.61 arc(15.33,49.42) v1(15.52,49.34)
  BOTTOM w0.102: U25.33 15.35,50.61 arc(15.34,50.57) 15.32,50.54 15.26,50.48 arc(15.24,50.45) 15.23,50.41 15.23,49.67 arc(15.24,49.63) 15.26,49.6 v1(15.52,49.34)
CSI2_D0_P: length 84
  TOP w0.102: J1.9 54.08,83.59 arc(54.05,83.45) 53.97,83.33 53.95,83.31 arc(53.87,83.19) 53.84,83.05 53.84,82.61 arc(53.91,82.46) 54.06,82.4 54.18,82.4 arc(54.26,82.43) 54.29,82.5 v1(54.29,82.55)
  L6_SIG2 w0.089: v1(14.6,49.34) 14.62,49.34 arc(14.83,49.43) 14.91,49.63 14.91,49.67 arc(15.1,50.14) 15.57,50.33 18.01,50.33 arc(18.23,50.42) 18.32,50.64 18.32,51.47 arc(18.98,52.13) 19.63,51.47 19.63,50.8 arc(19.94,50.49) 20.25,50.8 20.25,51.47 arc(20.91,52.12) 21.56,51.47 21.56,50.64 arc(21.65,50.42) 21.87,50.33 22.25,50.33 arc(23.01,50.48) 23.66,50.92 24.51,51.77 arc(24.96,52.44) 25.12,53.23 25.12,61.23 arc(25.23,61.8) 25.55,62.28 25.73,62.46 arc(25.98,62.84) 26.07,63.28 26.07,75.52 arc(26.33,76.81) 27.06,77.91 27.46,78.31 arc(27.55,78.53) 27.46,78.75 27.05,79.16 arc(26.86,79.63) 27.05,80.09 arc(27.52,80.28) 27.98,80.09 28.39,79.68 arc(28.61,79.59) 28.83,79.68 29.81,80.66 arc(30.55,81.15) 31.43,81.33 40.13,81.33 arc(40.76,81.2) 41.3,80.85 41.63,80.52 arc(42.11,80.2) 42.67,80.08 51.84,80.08 arc(52.19,80.15) 52.49,80.35 52.55,80.42 arc(52.81,80.59) 53.13,80.65 53.9,80.65 arc(54.07,80.69) 54.22,80.79 54.96,81.53 arc(55.12,81.77) 55.18,82.05 55.18,82.99 arc(55.09,83.22) 54.86,83.31 54.05,83.31 arc(53.93,83.26) 53.88,83.14 53.88,82.64 arc(53.94,82.5) 54.08,82.45 54.18,82.45 arc(54.26,82.48) v1(54.29,82.55)
  BOTTOM w0.102: v1(14.6,49.34) 14.9,49.64 arc(14.95,49.71) 14.96,49.8 14.96,50.41 arc(14.96,50.45) 14.93,50.48 14.88,50.54 arc(14.86,50.57) 14.85,50.61 U25.34
CSI2_D1_N: length 83.9
  TOP w0.102: v1(51.87,85.95) 51.91,85.95 arc(52.11,85.87) 52.19,85.67 52.19,85.36 arc(52.19,85.32) 52.16,85.29 52.11,85.23 arc(52.08,85.2) 52.08,85.16 J1.15
  L6_SIG2 w0.089: v1(51.87,85.95) 52.03,86.11 arc(52.05,86.15) 52.06,86.18 52.06,86.26 arc(52.22,86.64) 52.6,86.8 53.47,86.8 arc(53.85,86.64) 54.01,86.26 54.01,85.77 arc(53.88,85.12) 53.52,84.58 53.14,84.2 arc(52.79,83.67) 52.66,83.06 52.66,82.08 arc(52.34,81.3) 51.56,80.97 50.08,80.97 arc(49.6,81.07) 49.19,81.34 48.82,81.71 arc(48.55,81.89) 48.23,81.95 35.82,81.95 arc(35.24,82.07) 34.74,82.39 arc(34.41,82.62) 34.01,82.7 29.35,82.7 arc(28.59,82.55) 27.94,82.12 25.99,80.16 arc(25.61,79.59) 25.47,78.93 25.47,64.59 arc(25.32,63.81) 24.88,63.16 24.28,62.56 arc(23.91,62.01) 23.78,61.36 23.78,55.46 arc(23.65,54.78) 23.26,54.2 23.13,54.07 arc(22.39,53.57) 21.51,53.4 14.47,53.4 arc(14.16,53.34) 13.89,53.16 13.59,52.85 arc(13.36,52.52) 13.28,52.12 13.28,50.86 arc(13.31,50.71) 13.4,50.59 13.74,50.24 arc(13.95,49.94) 14.02,49.58 14.02,48.34 arc(14.03,48.29) 14.06,48.24 v1(14.3,48)
  BOTTOM w0.102: U25.35 14.35,50.61 arc(14.34,50.57) 14.32,50.54 14.26,50.48 arc(14.24,50.45) 14.23,50.41 14.23,49.81 arc(14.2,49.57) 14.11,49.36 arc(14.05,49.21) 14.03,49.05 14.03,48.27 arc(14.11,48.08) v1(14.3,48)
CSI2_D1_P: length 83.9
  TOP w0.102: v1(52.79,85.95) 52.79,86.02 arc(52.62,86.18) 52.46,86.02 52.46,85.36 arc(52.47,85.32) 52.49,85.29 52.55,85.23 arc(52.57,85.2) 52.58,85.16 J1.13
  L6_SIG2 w0.089: v1(52.79,85.95) 52.79,85.86 arc(52.75,85.78) 52.67,85.75 52.57,85.75 arc(52.45,85.8) 52.4,85.92 52.4,86.26 arc(52.46,86.4) 52.6,86.46 53.47,86.46 arc(53.61,86.4) 53.67,86.26 53.67,85.77 arc(53.57,85.26) 53.28,84.82 52.9,84.44 arc(52.47,83.81) 52.32,83.06 52.32,82.08 arc(52.1,81.54) 51.56,81.32 50.08,81.32 arc(49.73,81.39) 49.43,81.58 49.06,81.95 arc(48.68,82.2) 48.23,82.29 35.82,82.29 arc(35.37,82.38) 34.99,82.64 arc(34.54,82.94) 34.01,83.04 29.35,83.04 arc(28.45,82.86) 27.7,82.36 25.74,80.4 arc(25.29,79.73) 25.13,78.93 25.13,64.59 arc(25,63.95) 24.64,63.4 24.04,62.8 arc(23.6,62.14) 23.44,61.36 23.44,55.46 arc(23.33,54.91) 23.02,54.44 22.89,54.31 arc(22.26,53.89) 21.51,53.74 14.47,53.74 arc(14.03,53.66) 13.65,53.4 13.35,53.1 arc(13.05,52.65) 12.94,52.12 12.94,50.86 arc(13,50.58) 13.16,50.34 13.5,50 arc(13.63,49.81) 13.67,49.58 13.67,48.34 arc(13.66,48.29) 13.64,48.24 v1(13.39,48)
  BOTTOM w0.102: U25.36 13.85,50.61 arc(13.86,50.57) 13.88,50.54 13.93,50.48 arc(13.96,50.45) 13.96,50.41 13.96,49.81 arc(13.94,49.64) 13.88,49.49 arc(13.79,49.28) 13.76,49.05 13.76,48.29 arc(13.68,48.08) 13.47,48 v1(13.39,48)
CSI2_D2_N: length 84.4
  TOP w0.102: J1.19 50.58,83.53 arc(50.61,83.39) 50.69,83.27 50.7,83.25 arc(50.78,83.13) 50.81,82.99 50.81,82.71 arc(50.76,82.6) 50.65,82.55 v1(50.37,82.55)
  L6_SIG2 w0.089: v1(13.01,49.27) 12.97,49.27 arc(12.81,49.34) 12.74,49.5 12.74,49.61 arc(12.57,50.01) 12.17,50.18 10.92,50.18 arc(10.65,50.23) 10.43,50.38 10.33,50.48 arc(10.17,50.72) 10.11,51.01 10.11,52.7 arc(10.25,53.04) 10.59,53.18 11.07,53.18 arc(11.71,53.45) 11.98,54.09 11.98,54.23 arc(11.71,54.86) 11.08,55.12 10.59,55.12 arc(10.34,55.23) 10.24,55.48 10.24,57.56 arc(10.34,58.07) 10.63,58.51 12.46,60.34 arc(12.99,60.69) 13.62,60.82 17.23,60.82 arc(18.2,61.01) 19.01,61.56 23.42,65.96 arc(23.93,66.73) 24.12,67.64 24.12,79.53 arc(24.26,80.26) 24.68,80.88 24.77,80.97 arc(25.04,81.38) 25.13,81.85 25.13,83.34 arc(25.22,83.79) 25.48,84.17 25.6,84.3 arc(25.93,84.52) 26.31,84.59 33.33,84.59 arc(34.04,84.45) 34.65,84.05 arc(35.25,83.64) 35.97,83.5 42.75,83.5 arc(43.21,83.69) 43.4,84.15 43.4,84.64 arc(43.72,84.95) 44.03,84.64 44.03,84.15 arc(44.68,83.5) 45.34,84.15 45.34,84.64 arc(45.65,84.95) 45.96,84.64 45.96,84.15 arc(46.15,83.69) 46.61,83.5 50.29,83.5 arc(50.65,83.35) 50.8,82.99 50.8,82.46 arc(50.75,82.34) 50.63,82.3 50.53,82.3 arc(50.42,82.34) 50.37,82.46 v1(50.37,82.55)
  BOTTOM w0.102: v1(13.01,49.27) 12.95,49.27 arc(12.77,49.34) 12.7,49.52 arc(12.66,49.72) 12.55,49.89 12.3,50.13 arc(12.25,50.21) 12.23,50.3 12.23,50.41 arc(12.24,50.45) 12.26,50.48 12.32,50.54 arc(12.34,50.57) 12.35,50.61 U25.39
CSI2_D2_P: length 84.4
  TOP w0.102: J1.17 51.08,82.9 arc(51.1,82.77) 51.17,82.66 v1(51.29,82.55)
  L6_SIG2 w0.089: v1(12.09,49.27) 12.16,49.27 arc(12.33,49.34) 12.4,49.5 12.4,49.61 arc(12.33,49.77) 12.17,49.83 10.92,49.83 arc(10.52,49.91) 10.19,50.14 10.08,50.24 arc(9.85,50.59) 9.77,51.01 9.77,52.7 arc(10.01,53.29) 10.59,53.53 11.07,53.53 arc(11.47,53.69) 11.63,54.09 11.63,54.23 arc(11.47,54.62) 11.08,54.78 10.59,54.78 arc(10.1,54.98) 9.89,55.48 9.89,57.56 arc(10.02,58.2) 10.39,58.75 12.22,60.58 arc(12.86,61.01) 13.62,61.16 17.23,61.16 arc(18.06,61.33) 18.77,61.8 23.18,66.21 arc(23.62,66.86) 23.77,67.64 23.77,79.53 arc(23.94,80.39) 24.44,81.13 24.52,81.22 arc(24.72,81.51) 24.79,81.85 24.79,83.34 arc(24.9,83.92) 25.24,84.42 25.36,84.54 arc(25.8,84.83) 26.31,84.93 33.33,84.93 arc(34.18,84.77) 34.89,84.29 arc(35.39,83.96) 35.97,83.84 42.75,83.84 arc(42.97,83.93) 43.06,84.15 43.06,84.64 arc(43.72,85.29) 44.37,84.64 44.37,84.15 arc(44.68,83.84) 44.99,84.15 44.99,84.64 arc(45.65,85.29) 46.3,84.64 46.3,84.15 arc(46.39,83.93) 46.61,83.84 50.29,83.84 arc(50.89,83.59) 51.14,82.99 51.14,82.88 arc(51.18,82.71) 51.28,82.56 v1(51.29,82.55)
  BOTTOM w0.102: U25.40 11.85,50.61 arc(11.86,50.57) 11.88,50.54 11.93,50.48 arc(11.96,50.45) 11.96,50.41 11.96,50.3 arc(12,50.11) 12.11,49.94 12.36,49.7 arc(12.41,49.61) 12.43,49.52 arc(12.36,49.34) 12.19,49.27 v1(12.09,49.27)
CSI2_D3_N: length 84.1
  TOP w0.102: J1.23 49.08,85.05 arc(49.11,85.19) 49.19,85.31 49.2,85.32 arc(49.28,85.45) 49.31,85.59 49.31,85.95 arc(49.27,86.06) 49.16,86.11 49.02,86.11 arc(48.91,86.06) v1(48.87,85.95)
  L6_SIG2 w0.089: v1(12.04,48.02) 12.04,48.02 arc(11.85,48.1) 11.77,48.29 11.77,48.38 arc(11.6,48.81) 11.18,48.98 9.81,48.98 arc(9.56,49.03) 9.35,49.17 9.04,49.48 arc(8.9,49.69) 8.85,49.94 8.85,58.43 arc(8.94,58.9) 9.21,59.3 9.99,60.08 arc(10.33,60.59) 10.45,61.19 10.45,63.6 arc(10.5,63.86) 10.65,64.08 arc(10.8,64.19) 10.98,64.22 11.45,64.22 arc(11.75,64.28) 11.99,64.44 12.35,64.8 arc(12.92,65.18) 13.59,65.32 18.72,65.32 arc(19.37,65.44) 19.92,65.81 22.38,68.27 arc(22.77,68.86) 22.91,69.55 22.91,81.31 arc(22.97,81.63) 23.15,81.9 23.16,81.91 arc(23.35,82.19) 23.42,82.52 23.42,83.36 arc(23.53,83.94) 23.86,84.44 25.13,85.71 arc(25.41,85.9) 25.74,85.96 36.68,85.96 arc(37.37,86.1) 37.95,86.49 39.27,87.81 arc(39.66,88.07) 40.12,88.16 45,88.16 arc(45.4,88.24) 45.74,88.47 arc(45.82,88.52) 45.91,88.54 47.54,88.54 arc(48.82,88.01) 49.35,86.73 49.35,86.04 arc(49.29,85.89) 49.13,85.83 49,85.83 arc(48.91,85.86) v1(48.87,85.95)
  BOTTOM w0.102: U25.41 11.35,50.61 arc(11.34,50.57) 11.32,50.54 11.26,50.48 arc(11.24,50.45) 11.23,50.41 11.23,49.56 arc(11.29,49.25) 11.47,48.98 11.56,48.9 arc(11.69,48.7) 11.73,48.47 11.73,48.26 arc(11.8,48.09) 11.97,48.02 v1(12.04,48.02)
CSI2_D3_P: length 84.1
  TOP w0.102: v1(49.79,85.95) 49.67,85.84 arc(49.62,85.77) 49.59,85.69 arc(49.58,85.65) 49.58,85.61 J1.21
  L6_SIG2 w0.089: v1(11.13,48.02) 11.17,48.02 arc(11.35,48.1) 11.43,48.29 11.43,48.38 arc(11.36,48.56) 11.18,48.64 9.81,48.64 arc(9.43,48.71) 9.1,48.93 8.8,49.24 arc(8.58,49.56) 8.51,49.94 8.51,58.34 8.51,58.43 arc(8.63,59.03) 8.96,59.54 9.75,60.33 arc(10.02,60.72) 10.11,61.19 10.11,63.6 arc(10.19,63.99) 10.41,64.33 arc(10.67,64.5) 10.98,64.56 11.45,64.56 arc(11.62,64.6) 11.75,64.69 12.11,65.05 arc(12.79,65.5) 13.59,65.66 18.72,65.66 arc(19.24,65.76) 19.67,66.05 22.14,68.52 arc(22.45,68.99) 22.57,69.55 22.57,81.31 arc(22.66,81.76) 22.91,82.14 22.92,82.15 arc(23.03,82.32) 23.07,82.52 23.07,83.36 arc(23.22,84.08) 23.62,84.68 24.89,85.95 arc(25.28,86.21) 25.74,86.31 36.68,86.31 arc(37.24,86.42) 37.71,86.73 39.03,88.05 arc(39.53,88.39) 40.12,88.5 45,88.5 arc(45.27,88.56) 45.5,88.71 arc(45.69,88.84) 45.91,88.88 47.54,88.88 arc(49.06,88.25) 49.69,86.73 49.69,86.18 arc(49.7,86.12) 49.71,86.07 arc(49.74,86.01) v1(49.79,85.95)
  BOTTOM w0.102: v1(11.13,48.02) 11.23,48.02 arc(11.4,48.09) 11.47,48.26 11.47,48.47 arc(11.44,48.6) 11.37,48.71 11.28,48.8 arc(11.05,49.14) 10.96,49.56 10.96,50.41 arc(10.96,50.45) 10.93,50.48 10.88,50.54 arc(10.86,50.57) 10.85,50.61 U25.42
CSI_TX_CLK_N: length 34.8
  TOP w0.102: v1(39.41,171.69) 39.41,171.84 arc(39.35,171.99) 39.19,172.05 38.96,172.05 arc(38.66,172.18) 38.53,172.48 38.53,173.01 arc(38.58,173.22) 38.7,173.4 45,179.71 arc(45.52,180.49) 45.71,181.41 45.71,182.34 45.71,183.02 arc(45.89,183.46) 46.33,183.64 47.5,183.64 arc(47.85,184) 47.5,184.36 46.33,184.36 arc(45.89,184.54) 45.71,184.98 45.71,186.33 arc(45.66,186.56) 45.53,186.76 arc(45.38,186.98) 45.33,187.25 45.33,187.45 arc(45.24,187.66) 45.03,187.75 v1(45.02,187.75)
  BOTTOM w0.102: J20.7 45.25,188.36 arc(45.26,188.32) 45.28,188.28 45.34,188.23 arc(45.36,188.19) 45.37,188.16 45.37,187.96 arc(45.31,187.81) 45.16,187.75 v1(45.02,187.75) ; v1(39.41,171.69) 39.11,171.99 arc(39.08,172.01) 39.04,172.02 35.23,172.02 arc(34.37,171.85) 33.65,171.36 32.97,170.68 arc(32.67,170.23) 32.56,169.7 32.56,168.84 arc(32.57,168.8) 32.59,168.76 32.65,168.71 arc(32.67,168.67) 32.68,168.64 U32.6
CSI_TX_CLK_P: length 34.8
  TOP w0.102: v1(45.94,187.75) 45.89,187.75 arc(45.68,187.66) 45.59,187.45 45.59,187.25 arc(45.63,187.08) 45.72,186.94 arc(45.91,186.66) 45.97,186.33 45.97,184.98 arc(46.08,184.73) 46.33,184.62 47.5,184.62 arc(48.12,184) 47.5,183.38 46.33,183.38 arc(46.08,183.27) 45.97,183.02 45.97,182.61 45.97,181.41 arc(45.77,180.39) 45.19,179.52 38.89,173.22 arc(38.82,173.12) 38.8,173.01 38.8,172.48 arc(38.85,172.37) 38.96,172.32 39.27,172.32 arc(39.37,172.36) 39.41,172.46 v1(39.41,172.61)
  BOTTOM w0.102: v1(39.41,172.61) 39.11,172.31 arc(39.08,172.29) 39.04,172.28 35.23,172.28 arc(34.27,172.09) 33.46,171.55 32.78,170.87 arc(32.42,170.33) 32.3,169.7 32.3,168.84 arc(32.29,168.8) 32.27,168.76 32.21,168.71 arc(32.19,168.67) 32.18,168.64 U32.5 ; v1(45.94,187.75) 45.85,187.75 arc(45.7,187.81) 45.64,187.96 45.64,188.16 arc(45.65,188.19) 45.67,188.23 45.73,188.28 arc(45.75,188.32) 45.75,188.36 J20.5
CSI_TX_D0_N: length 35.1
  TOP w0.102: v1(32.1,172.22) 31.82,172.5 arc(31.77,172.53) 31.71,172.54 31.46,172.54 arc(30.91,172.77) 30.69,173.31 30.69,175.54 arc(30.89,176.55) 31.47,177.41 33.92,179.87 arc(35.2,180.73) 36.72,181.03 38.72,181.03 arc(39.16,180.85) 39.34,180.41 39.34,180.03 arc(39.7,179.68) 40.05,180.03 40.05,180.41 arc(40.24,180.85) 40.68,181.03 41.06,181.03 arc(43.19,181.91) 44.07,184.04 44.07,185.95 arc(44.04,186.12) 43.94,186.26 arc(43.85,186.4) 43.81,186.56 43.81,186.84 arc(43.74,187.03) v1(43.55,187.1)
  BOTTOM w0.102: U32.4 31.68,168.64 arc(31.67,168.67) 31.65,168.71 31.59,168.76 arc(31.57,168.8) 31.56,168.84 31.56,169.06 arc(31.45,169.61) 31.14,170.08 31.09,170.13 arc(31,170.27) 30.96,170.44 30.96,172.01 arc(31.12,172.39) 31.5,172.54 31.73,172.54 arc(31.77,172.53) 31.81,172.51 v1(32.1,172.22) ; v1(43.55,187.1) 43.84,187.4 43.86,187.42 arc(43.87,187.45) 43.87,187.47 43.87,188.16 arc(43.86,188.19) 43.84,188.23 43.78,188.28 arc(43.76,188.32) 43.75,188.36 J20.11
CSI_TX_D0_P: length 35.2
  TOP w0.102: v1(32.1,173.13) 31.82,172.86 arc(31.77,172.82) 31.71,172.81 31.46,172.81 arc(31.1,172.96) 30.95,173.31 30.95,175.54 arc(31.14,176.45) 31.65,177.23 34.11,179.68 arc(35.31,180.48) 36.72,180.76 38.72,180.76 arc(38.97,180.66) 39.08,180.41 39.08,180.03 arc(39.7,179.41) 40.32,180.03 40.32,180.41 arc(40.43,180.66) 40.68,180.76 41.06,180.76 arc(43.38,181.72) 44.34,184.04 44.34,185.95 arc(44.28,186.22) 44.13,186.44 arc(44.09,186.5) 44.08,186.56 44.08,186.82 arc(44.17,187.02) 44.37,187.1 v1(44.46,187.1)
  BOTTOM w0.102: J20.9 44.25,188.36 arc(44.25,188.32) 44.23,188.28 44.17,188.23 arc(44.15,188.19) 44.14,188.16 44.14,187.47 arc(44.14,187.45) 44.15,187.42 44.17,187.4 v1(44.46,187.1) ; v1(32.1,173.13) 31.81,172.84 arc(31.77,172.82) 31.73,172.81 31.5,172.81 arc(30.93,172.57) 30.7,172.01 30.7,170.44 arc(30.75,170.17) 30.9,169.94 30.95,169.89 arc(31.21,169.51) 31.3,169.06 31.3,168.84 arc(31.29,168.8) 31.27,168.76 31.21,168.71 arc(31.19,168.67) 31.18,168.64 U32.3
CSI_TX_D1_N: length 35.1
  TOP w0.102: v1(42.02,187.75) 42.18,187.59 arc(42.26,187.47) 42.29,187.32 42.29,184.15 arc(41.77,182.89) 40.51,182.37 36.05,182.37 arc(34.84,182.13) 33.82,181.45 30.66,178.29 arc(29.82,177.02) 29.52,175.53 29.52,171.98 arc(29.89,171.09) 30.78,170.72 31.23,170.72 arc(31.49,170.61) 31.59,170.36 31.59,170.12 arc(31.47,169.83) 31.18,169.71 29.61,169.71 arc(29.57,169.71) 29.54,169.74 v1(29.25,170.03)
  BOTTOM w0.102: v1(42.02,187.75) 42.16,187.75 arc(42.31,187.81) 42.37,187.96 42.37,188.16 arc(42.36,188.19) 42.34,188.23 42.28,188.28 arc(42.26,188.32) 42.25,188.36 J20.15 ; v1(29.25,170.03) 29.54,169.74 arc(29.57,169.71) 29.61,169.71 29.95,169.71 arc(30.38,169.52) 30.56,169.09 30.56,168.84 arc(30.57,168.8) 30.59,168.76 30.65,168.71 arc(30.67,168.67) 30.68,168.64 U32.2
CSI_TX_D1_P: length 35.1
  TOP w0.102: v1(29.25,169.12) 29.54,169.41 arc(29.57,169.43) 29.61,169.44 31.18,169.44 arc(31.66,169.64) 31.86,170.12 31.86,170.36 arc(31.68,170.8) 31.23,170.98 30.78,170.98 arc(30.08,171.27) 29.79,171.98 29.79,175.53 arc(30.06,176.92) 30.85,178.1 34.01,181.26 arc(34.95,181.89) 36.05,182.11 40.51,182.11 arc(41.96,182.71) 42.56,184.15 42.56,187.32 arc(42.57,187.37) 42.59,187.41 v1(42.94,187.75)
  BOTTOM w0.102: J20.13 42.75,188.36 arc(42.75,188.32) 42.73,188.28 42.67,188.23 arc(42.65,188.19) 42.64,188.16 42.64,187.96 arc(42.7,187.81) 42.85,187.75 v1(42.94,187.75) ; U32.1 30.18,168.64 arc(30.19,168.67) 30.21,168.71 30.27,168.76 arc(30.29,168.8) 30.3,168.84 30.3,169.09 arc(30.19,169.34) 29.95,169.44 29.61,169.44 arc(29.57,169.43) 29.54,169.41 v1(29.25,169.12)
CSI_TX_D2_N: length 34.9
  TOP w0.102: v1(40.55,187.1) 40.59,187.1 arc(40.8,187.02) 40.88,186.82 40.88,184.31 arc(40.65,183.76) 40.1,183.53 35.09,183.53 arc(34.22,183.36) 33.49,182.86 28.39,177.77 arc(28.06,177.27) 27.95,176.69 27.95,173.32 arc(27.89,173.2) 27.77,173.14 27.44,173.14 arc(27.26,173.26) v1(27.3,173.47)
  BOTTOM w0.102: v1(40.55,187.1) 40.84,187.4 40.86,187.42 arc(40.87,187.45) 40.87,187.47 40.87,188.16 arc(40.86,188.19) 40.84,188.23 40.78,188.28 arc(40.76,188.32) 40.75,188.36 J20.19 ; U32.32 28.85,167.31 arc(28.81,167.3) 28.78,167.28 28.72,167.22 arc(28.69,167.2) 28.65,167.19 28.62,167.19 arc(28.35,167.3) 28.24,167.56 28.24,170.46 arc(28.33,170.87) 28.56,171.22 28.73,171.39 arc(28.83,171.54) 28.86,171.71 28.86,172.26 arc(28.6,172.88) 27.97,173.14 27.44,173.14 arc(27.26,173.26) v1(27.3,173.47)
CSI_TX_D2_P: length 34.9
  TOP w0.102: v1(27.3,172.55) 27.6,172.85 arc(27.63,172.87) 27.67,172.88 27.77,172.88 arc(28.08,173.01) 28.21,173.32 28.21,176.69 arc(28.31,177.17) 28.58,177.58 33.68,182.68 arc(34.33,183.11) 35.09,183.26 40.1,183.26 arc(40.84,183.57) 41.15,184.31 41.15,186.82 arc(41.23,187.02) 41.44,187.1 v1(41.46,187.1)
  BOTTOM w0.102: v1(41.46,187.1) 41.17,187.4 41.15,187.42 arc(41.14,187.45) 41.14,187.47 41.14,188.16 arc(41.15,188.19) 41.17,188.23 41.23,188.28 arc(41.25,188.32) 41.25,188.36 J20.17 ; U32.31 28.85,166.81 arc(28.81,166.82) 28.78,166.84 28.72,166.9 arc(28.69,166.92) 28.65,166.93 28.62,166.93 arc(28.16,167.11) 27.98,167.56 27.98,170.46 arc(28.08,170.97) 28.37,171.41 28.54,171.58 arc(28.58,171.64) 28.59,171.71 28.59,172.26 arc(28.41,172.7) 27.97,172.88 27.67,172.88 arc(27.63,172.87) 27.6,172.85 v1(27.3,172.55)
CSI_TX_D3_N: length 34.9
  TOP w0.102: v1(25.44,171.36) 25.44,171.29 arc(25.52,171.11) 25.69,171.03 25.85,171.03 arc(26.04,171.12) 26.12,171.31 26.12,174.59 arc(26.61,177.03) 27.99,179.09 32.51,183.62 arc(34.1,184.68) 35.97,185.05 36.79,185.05 arc(38.02,185.3) 39.05,185.99 arc(39.28,186.33) 39.36,186.72 39.36,187.42 arc(39.26,187.65) v1(39.02,187.75)
  BOTTOM w0.102: v1(39.02,187.75) 39.16,187.75 arc(39.31,187.81) 39.37,187.96 39.37,188.16 arc(39.36,188.19) 39.34,188.23 39.28,188.28 arc(39.26,188.32) 39.26,188.36 J20.23 ; U32.30 28.85,166.31 arc(28.81,166.3) 28.78,166.28 28.72,166.22 arc(28.69,166.2) 28.65,166.19 28.5,166.19 arc(28.4,166.21) 28.32,166.27 27.39,167.2 arc(27.18,167.52) 27.1,167.89 27.1,170.13 arc(26.84,170.77) 26.19,171.04 25.44,171.04 arc(25.28,171.2) v1(25.44,171.36)
